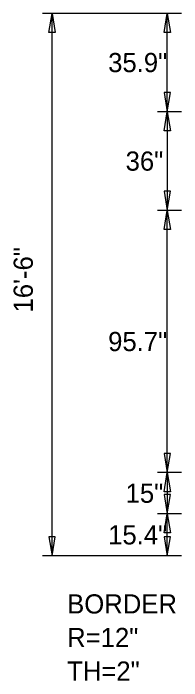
# Model space of a CAD drawing. Extents: x 2149961 to 2150220, y 145114 to 145240.
# Drawn here: x 2150191.92 to 2150197.04, y 145126.52 to 145146.82 of the extents above; entities that cross this region are included whole.
import ezdxf

# ---------------------------------------------------------------- set-up
doc = ezdxf.new("R2010")
doc.units = 0
doc.layers.add('GSDIMS', color=7, linetype='Continuous')

msp = doc.modelspace()

# ---------------------------------------------------------------- linework, layer by layer
at = {"layer": 'GSDIMS'}
for p, q in [((2150193.535, 145146.817), (2150192.806, 145146.817)), ((2150193.098, 145130.317), (2150193.098, 145146.817)), ((2150197.035, 145146.817), (2150193.535, 145146.817)), ((2150197.035, 145146.817), (2150196.306, 145146.817)), ((2150196.598, 145143.825), (2150196.598, 145146.817)), ((2150197.035, 145143.825), (2150196.306, 145143.825)), ((2150197.035, 145143.825), (2150196.306, 145143.825)), ((2150196.598, 145143.825), (2150196.598, 145140.825)), ((2150197.035, 145140.825), (2150196.306, 145140.825)), ((2150197.035, 145140.825), (2150196.306, 145140.825)), ((2150196.598, 145132.85), (2150196.598, 145140.825)), ((2150197.035, 145132.85), (2150196.306, 145132.85)), ((2150197.035, 145132.85), (2150196.306, 145132.85)), ((2150196.598, 145132.85), (2150196.598, 145131.6)), ((2150197.035, 145131.6), (2150196.306, 145131.6)), ((2150197.035, 145131.6), (2150196.306, 145131.6)), ((2150196.598, 145130.317), (2150196.598, 145131.6)), ((2150193.535, 145130.317), (2150192.806, 145130.317)), ((2150197.035, 145130.317), (2150193.535, 145130.317)), ((2150197.035, 145130.317), (2150196.306, 145130.317))]:
    msp.add_line(p, q, dxfattribs=at)
for points in [[(2150193.098, 145146.817), (2150193.195, 145146.233), (2150193, 145146.233)], [(2150196.598, 145146.817), (2150196.695, 145146.233), (2150196.5, 145146.233)], [(2150196.598, 145143.825), (2150196.695, 145144.408), (2150196.5, 145144.408)], [(2150196.598, 145143.825), (2150196.695, 145143.241), (2150196.5, 145143.241)], [(2150196.598, 145140.825), (2150196.695, 145141.408), (2150196.5, 145141.408)], [(2150196.598, 145140.825), (2150196.695, 145140.241), (2150196.5, 145140.241)], [(2150196.598, 145132.85), (2150196.695, 145133.433), (2150196.5, 145133.433)], [(2150196.598, 145132.85), (2150196.695, 145132.267), (2150196.5, 145132.267)], [(2150196.598, 145131.6), (2150196.695, 145132.183), (2150196.5, 145132.183)], [(2150196.598, 145131.6), (2150196.695, 145131.017), (2150196.5, 145131.017)], [(2150193.098, 145130.317), (2150193.195, 145130.9), (2150193, 145130.9)], [(2150196.598, 145130.317), (2150196.695, 145130.9), (2150196.5, 145130.9)]]:
    msp.add_lwpolyline(points, close=True, dxfattribs=at)

# ---------------------------------------------------------------- texts
for s, p in [('35.9"', (2150194.802, 145145.029)), ('36"', (2150195.333, 145142.033)), ('95.7"', (2150194.802, 145136.546)), ('15"', (2150195.333, 145131.933)), ('15.4"', (2150194.802, 145130.667)), ('BORDER', (2150193.556, 145128.567)), ('R=12"', (2150193.556, 145127.546)), ('TH=2"', (2150193.556, 145126.525))]:
    msp.add_text(s, height=0.5833, dxfattribs=at).set_placement(p)
msp.add_text('16\'-6"', height=0.5833, rotation=90, dxfattribs=at).set_placement((2150192.514, 145137.721))

doc.saveas('drawing.dxf')
